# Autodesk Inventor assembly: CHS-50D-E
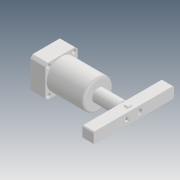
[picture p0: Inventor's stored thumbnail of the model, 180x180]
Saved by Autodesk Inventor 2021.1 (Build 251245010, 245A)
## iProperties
Created: 2019-04
Part Number: CHS-50D-E
Description: STEP AP203
Document SubType Name: Assembly
Designer: user
Title: chs-50de_asm.STEP
Revision Number: ÈÎºÎ
Sending System: SolidWorks 2017
Preprocessor: SwSTEP 2.0
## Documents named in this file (6)
- D:\Vault_2016\Projekty\Clamptek\Hydraulic\CHS\CHS-50\Inventor\CHS-50D-E\CHS-50D-E.iam
- D:\Vault_2016\Projekty\Clamptek\Hydraulic\CHS\CHS-50\Inventor\CHS-50D-E\CHS-50-EBT.ipt
- D:\Vault_2016\Projekty\Clamptek\Hydraulic\CHS\CHS-50\Inventor\CHS-50D-E\CHS-50-EDHSG.ipt
- D:\Vault_2016\Projekty\Clamptek\Hydraulic\CHS\CHS-50\Inventor\CHS-50D-E\CHS-50DYB_1.ipt
- D:\Vault_2016\Projekty\Clamptek\Hydraulic\CHS\CHS-50\Inventor\CHS-50D-E\Ïú.ipt
- D:\Vault_2016\Projekty\Clamptek\Hydraulic\CHS\CHS-50\Inventor\CHS-50D-E\ÖáÓÃµ²È¦.ipt
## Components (6 placed, 6 different names)
1. CHS-50-EBT_1
2. CHS-50-EDHSG_2
3. CHS-50DYB_1_3
4. Ïú_4
5. ÖáÓÃµ²È¦_5
6. ÖáÓÃµ²È¦_6
